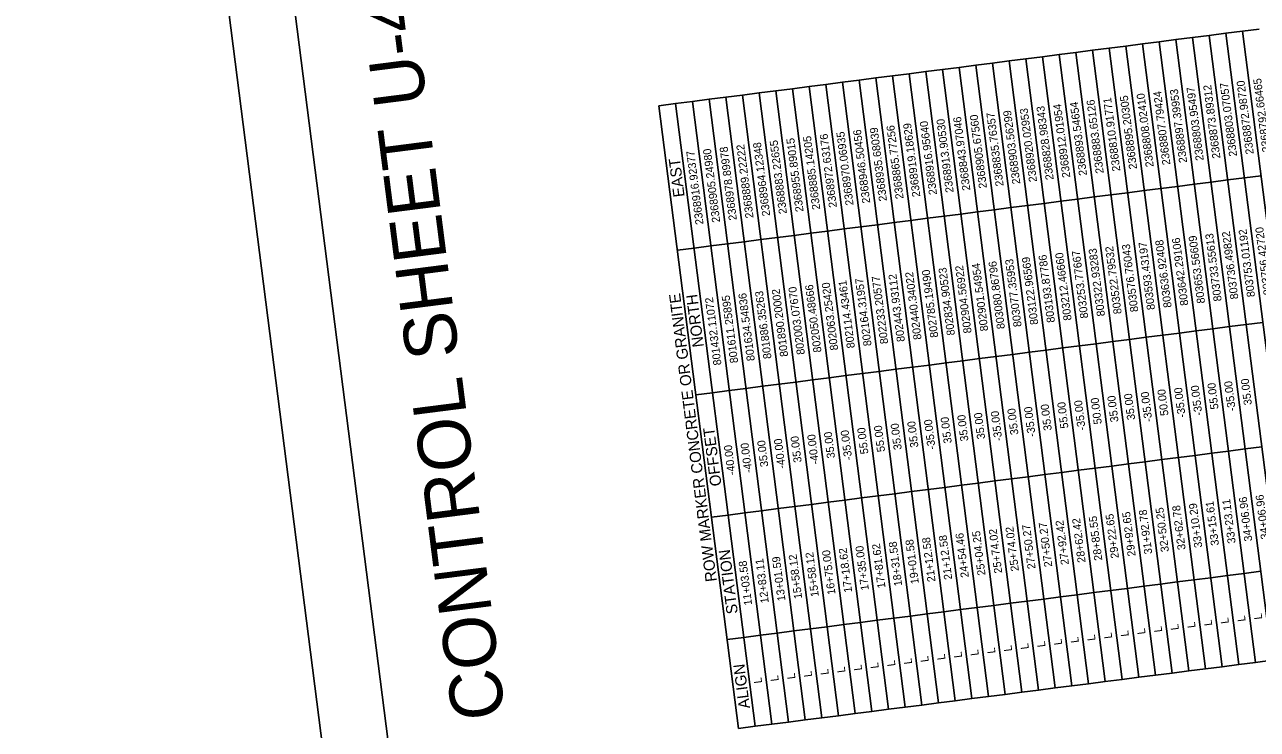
# Model space of a CAD drawing. Extents: x 2364621 to 2374814, y 792603 to 806745.
# Drawn here: x 2364621 to 2368280, y 798784 to 800875 of the extents above; entities that cross this region are included whole.
import ezdxf

# ---------------------------------------------------------------- set-up
doc = ezdxf.new("R2010")
doc.units = 0
for name, color, linetype in [('CTL Sheet Border CELL', 7, 'Continuous'), ('CTL Sheet Notes CELL', 7, 'Continuous'), ('CTL Sheet Table Cell', 7, 'Continuous'), ('CTL Sheet Text', 7, 'Continuous'), ('Scratch_Level_0', 7, 'Continuous')]:
    doc.layers.add(name, color=color, linetype=linetype)

msp = doc.modelspace()

# ---------------------------------------------------------------- linework, layer by layer
at = {"layer": 'CTL Sheet Border CELL'}
msp.add_lwpolyline([(2364831.4, 805549.1), (2366316.3, 793922.1), (2374455.2, 794961.6), (2372970.2, 806588.6)], close=True, dxfattribs=at)
at = {"layer": 'CTL Sheet Table Cell'}
for p, q in [((2367988.5, 800824.4), (2368038, 800830.7)), ((2368038, 800830.7), (2368087.5, 800837.1)), ((2368274, 798983), (2368038, 800830.7)), ((2368087.5, 800837.1), (2368137, 800843.4)), ((2368323.5, 798989.3), (2368087.5, 800837.1)), ((2368137, 800843.4), (2368186.5, 800849.7)), ((2368373, 798995.6), (2368137, 800843.4)), ((2368186.5, 800849.7), (2368236, 800856)), ((2368422.5, 799001.9), (2368186.5, 800849.7)), ((2368236, 800856), (2368285.5, 800862.3)), ((2368472, 799008.2), (2368236, 800856)), ((2367691.6, 800786.5), (2367741.1, 800792.8)), ((2367741.1, 800792.8), (2367790.6, 800799.1)), ((2367977.1, 798945), (2367741.1, 800792.8)), ((2367790.6, 800799.1), (2367840.1, 800805.5)), ((2368026.6, 798951.4), (2367790.6, 800799.1)), ((2367840.1, 800805.5), (2367889.5, 800811.8)), ((2368076.1, 798957.7), (2367840.1, 800805.5)), ((2367889.5, 800811.8), (2367939, 800818.1)), ((2368125.5, 798964), (2367889.5, 800811.8)), ((2367939, 800818.1), (2367988.5, 800824.4)), ((2368175, 798970.3), (2367939, 800818.1)), ((2368224.5, 798976.6), (2367988.5, 800824.4)), ((2367394.6, 800748.6), (2367444.1, 800754.9)), ((2367444.1, 800754.9), (2367493.6, 800761.2)), ((2367680.1, 798907.1), (2367444.1, 800754.9)), ((2367493.6, 800761.2), (2367543.1, 800767.5)), ((2367729.6, 798913.4), (2367493.6, 800761.2)), ((2367543.1, 800767.5), (2367592.6, 800773.8)), ((2367779.1, 798919.8), (2367543.1, 800767.5)), ((2367592.6, 800773.8), (2367642.1, 800780.2)), ((2367828.6, 798926.1), (2367592.6, 800773.8)), ((2367642.1, 800780.2), (2367691.6, 800786.5)), ((2367878.1, 798932.4), (2367642.1, 800780.2)), ((2367927.6, 798938.7), (2367691.6, 800786.5)), ((2367147.1, 800717), (2367196.6, 800723.3)), ((2367196.6, 800723.3), (2367246.1, 800729.6)), ((2367432.6, 798875.5), (2367196.6, 800723.3)), ((2367246.1, 800729.6), (2367295.6, 800735.9)), ((2367482.1, 798881.8), (2367246.1, 800729.6)), ((2367295.6, 800735.9), (2367345.1, 800742.2)), ((2367531.6, 798888.1), (2367295.6, 800735.9)), ((2367345.1, 800742.2), (2367394.6, 800748.6)), ((2367581.1, 798894.5), (2367345.1, 800742.2)), ((2367630.6, 798900.8), (2367394.6, 800748.6)), ((2366850.2, 800679), (2366899.7, 800685.3)), ((2366899.7, 800685.3), (2366949.2, 800691.7)), ((2367135.7, 798837.6), (2366899.7, 800685.3)), ((2366949.2, 800691.7), (2366998.7, 800698)), ((2367185.2, 798843.9), (2366949.2, 800691.7)), ((2366998.7, 800698), (2367048.2, 800704.3)), ((2367234.7, 798850.2), (2366998.7, 800698)), ((2367048.2, 800704.3), (2367097.6, 800710.6)), ((2367284.1, 798856.5), (2367048.2, 800704.3)), ((2367097.6, 800710.6), (2367147.1, 800717)), ((2367333.6, 798862.9), (2367097.6, 800710.6)), ((2367383.1, 798869.2), (2367147.1, 800717)), ((2366553.2, 800641.1), (2366602.7, 800647.4)), ((2366602.7, 800647.4), (2366652.2, 800653.7)), ((2366838.7, 798799.6), (2366602.7, 800647.4)), ((2366652.2, 800653.7), (2366701.7, 800660.1)), ((2366888.2, 798806), (2366652.2, 800653.7)), ((2366701.7, 800660.1), (2366751.2, 800666.4)), ((2366937.7, 798812.3), (2366701.7, 800660.1)), ((2366751.2, 800666.4), (2366800.7, 800672.7)), ((2366987.2, 798818.6), (2366751.2, 800666.4)), ((2366800.7, 800672.7), (2366850.2, 800679)), ((2367036.7, 798824.9), (2366800.7, 800672.7)), ((2367086.2, 798831.3), (2366850.2, 800679)), ((2366503.7, 800634.8), (2366553.2, 800641.1)), ((2366739.7, 798787), (2366503.7, 800634.8)), ((2366789.2, 798793.3), (2366553.2, 800641.1)), ((2368241.3, 800420.8), (2368290.8, 800427.1)), ((2367944.3, 800382.8), (2367993.8, 800389.1)), ((2367993.8, 800389.1), (2368043.3, 800395.5)), ((2368043.3, 800395.5), (2368092.8, 800401.8)), ((2368092.8, 800401.8), (2368142.3, 800408.1)), ((2368142.3, 800408.1), (2368191.8, 800414.4)), ((2368191.8, 800414.4), (2368241.3, 800420.8)), ((2367647.4, 800344.9), (2367696.9, 800351.2)), ((2367696.9, 800351.2), (2367746.4, 800357.5)), ((2367746.4, 800357.5), (2367795.9, 800363.9)), ((2367795.9, 800363.9), (2367845.3, 800370.2)), ((2367845.3, 800370.2), (2367894.8, 800376.5)), ((2367894.8, 800376.5), (2367944.3, 800382.8)), ((2367399.9, 800313.3), (2367449.4, 800319.6)), ((2367449.4, 800319.6), (2367498.9, 800325.9)), ((2367498.9, 800325.9), (2367548.4, 800332.3)), ((2367548.4, 800332.3), (2367597.9, 800338.6)), ((2367597.9, 800338.6), (2367647.4, 800344.9)), ((2367102.9, 800275.4), (2367152.4, 800281.7)), ((2367152.4, 800281.7), (2367201.9, 800288)), ((2367201.9, 800288), (2367251.4, 800294.3)), ((2367251.4, 800294.3), (2367300.9, 800300.6)), ((2367300.9, 800300.6), (2367350.4, 800307)), ((2367350.4, 800307), (2367399.9, 800313.3)), ((2366806, 800237.4), (2366855.5, 800243.8)), ((2366855.5, 800243.8), (2366905, 800250.1)), ((2366905, 800250.1), (2366954.5, 800256.4)), ((2366954.5, 800256.4), (2367003.9, 800262.7)), ((2367003.9, 800262.7), (2367053.4, 800269)), ((2367053.4, 800269), (2367102.9, 800275.4)), ((2366558.5, 800205.8), (2366608, 800212.2)), ((2366608, 800212.2), (2366657.5, 800218.5)), ((2366657.5, 800218.5), (2366707, 800224.8)), ((2366707, 800224.8), (2366756.5, 800231.1)), ((2366756.5, 800231.1), (2366806, 800237.4)), ((2368197.1, 799979.2), (2368246.6, 799985.5)), ((2368246.6, 799985.5), (2368296.1, 799991.8)), ((2367949.6, 799947.6), (2367999.1, 799953.9)), ((2367999.1, 799953.9), (2368048.6, 799960.2)), ((2368048.6, 799960.2), (2368098.1, 799966.5)), ((2368098.1, 799966.5), (2368147.6, 799972.8)), ((2368147.6, 799972.8), (2368197.1, 799979.2)), ((2367652.7, 799909.6), (2367702.2, 799916)), ((2367702.2, 799916), (2367751.6, 799922.3)), ((2367751.6, 799922.3), (2367801.1, 799928.6)), ((2367801.1, 799928.6), (2367850.6, 799934.9)), ((2367850.6, 799934.9), (2367900.1, 799941.2)), ((2367900.1, 799941.2), (2367949.6, 799947.6)), ((2367355.7, 799871.7), (2367405.2, 799878)), ((2367405.2, 799878), (2367454.7, 799884.3)), ((2367454.7, 799884.3), (2367504.2, 799890.7)), ((2367504.2, 799890.7), (2367553.7, 799897)), ((2367553.7, 799897), (2367603.2, 799903.3)), ((2367603.2, 799903.3), (2367652.7, 799909.6)), ((2367058.7, 799833.8), (2367108.2, 799840.1)), ((2367108.2, 799840.1), (2367157.7, 799846.4)), ((2367157.7, 799846.4), (2367207.2, 799852.7)), ((2367207.2, 799852.7), (2367256.7, 799859.1)), ((2367256.7, 799859.1), (2367306.2, 799865.4)), ((2367306.2, 799865.4), (2367355.7, 799871.7)), ((2366811.3, 799802.2), (2366860.8, 799808.5)), ((2366860.8, 799808.5), (2366910.3, 799814.8)), ((2366910.3, 799814.8), (2366959.7, 799821.1)), ((2366959.7, 799821.1), (2367009.2, 799827.5)), ((2367009.2, 799827.5), (2367058.7, 799833.8)), ((2366613.3, 799776.9), (2366662.8, 799783.2)), ((2366662.8, 799783.2), (2366712.3, 799789.5)), ((2366712.3, 799789.5), (2366761.8, 799795.8)), ((2366761.8, 799795.8), (2366811.3, 799802.2)), ((2368243.4, 799616.2), (2368292.9, 799622.5)), ((2367946.5, 799578.3), (2367996, 799584.6)), ((2367996, 799584.6), (2368045.5, 799590.9)), ((2368045.5, 799590.9), (2368095, 799597.2)), ((2368095, 799597.2), (2368144.5, 799603.6)), ((2368144.5, 799603.6), (2368194, 799609.9)), ((2368194, 799609.9), (2368243.4, 799616.2)), ((2367649.5, 799540.4), (2367699, 799546.7)), ((2367699, 799546.7), (2367748.5, 799553)), ((2367748.5, 799553), (2367798, 799559.3)), ((2367798, 799559.3), (2367847.5, 799565.6)), ((2367847.5, 799565.6), (2367897, 799572)), ((2367897, 799572), (2367946.5, 799578.3)), ((2367402.1, 799508.7), (2367451.5, 799515.1)), ((2367451.5, 799515.1), (2367501, 799521.4)), ((2367501, 799521.4), (2367550.5, 799527.7)), ((2367550.5, 799527.7), (2367600, 799534)), ((2367600, 799534), (2367649.5, 799540.4)), ((2367105.1, 799470.8), (2367154.6, 799477.1)), ((2367154.6, 799477.1), (2367204.1, 799483.5)), ((2367204.1, 799483.5), (2367253.6, 799489.8)), ((2367253.6, 799489.8), (2367303.1, 799496.1)), ((2367303.1, 799496.1), (2367352.6, 799502.4)), ((2367352.6, 799502.4), (2367402.1, 799508.7)), ((2366808.1, 799432.9), (2366857.6, 799439.2)), ((2366857.6, 799439.2), (2366907.1, 799445.5)), ((2366907.1, 799445.5), (2366956.6, 799451.9)), ((2366956.6, 799451.9), (2367006.1, 799458.2)), ((2367006.1, 799458.2), (2367055.6, 799464.5)), ((2367055.6, 799464.5), (2367105.1, 799470.8)), ((2366659.6, 799413.9), (2366709.1, 799420.2)), ((2366709.1, 799420.2), (2366758.6, 799426.6)), ((2366758.6, 799426.6), (2366808.1, 799432.9)), ((2367992.8, 799215.3), (2368042.3, 799221.6)), ((2368042.3, 799221.6), (2368091.8, 799228)), ((2368091.8, 799228), (2368141.3, 799234.3)), ((2368141.3, 799234.3), (2368190.8, 799240.6)), ((2368190.8, 799240.6), (2368240.3, 799246.9)), ((2368240.3, 799246.9), (2368289.8, 799253.3)), ((2367695.9, 799177.4), (2367745.4, 799183.7)), ((2367745.4, 799183.7), (2367794.9, 799190)), ((2367794.9, 799190), (2367844.4, 799196.4)), ((2367844.4, 799196.4), (2367893.9, 799202.7)), ((2367893.9, 799202.7), (2367943.3, 799209)), ((2367943.3, 799209), (2367992.8, 799215.3)), ((2367398.9, 799139.5), (2367448.4, 799145.8)), ((2367448.4, 799145.8), (2367497.9, 799152.1)), ((2367497.9, 799152.1), (2367547.4, 799158.4)), ((2367547.4, 799158.4), (2367596.9, 799164.8)), ((2367596.9, 799164.8), (2367646.4, 799171.1)), ((2367646.4, 799171.1), (2367695.9, 799177.4)), ((2367102, 799101.5), (2367151.4, 799107.9)), ((2367151.4, 799107.9), (2367200.9, 799114.2)), ((2367200.9, 799114.2), (2367250.4, 799120.5)), ((2367250.4, 799120.5), (2367299.9, 799126.8)), ((2367299.9, 799126.8), (2367349.4, 799133.1)), ((2367349.4, 799133.1), (2367398.9, 799139.5)), ((2366854.5, 799069.9), (2366904, 799076.3)), ((2366904, 799076.3), (2366953.5, 799082.6)), ((2366953.5, 799082.6), (2367003, 799088.9)), ((2367003, 799088.9), (2367052.5, 799095.2)), ((2367052.5, 799095.2), (2367102, 799101.5)), ((2366706, 799051), (2366755.5, 799057.3)), ((2366755.5, 799057.3), (2366805, 799063.6)), ((2366805, 799063.6), (2366854.5, 799069.9)), ((2368076.1, 798957.7), (2368125.5, 798964)), ((2368125.5, 798964), (2368175, 798970.3)), ((2368175, 798970.3), (2368224.5, 798976.6)), ((2368224.5, 798976.6), (2368274, 798983)), ((2368274, 798983), (2368323.5, 798989.3)), ((2367779.1, 798919.8), (2367828.6, 798926.1)), ((2367828.6, 798926.1), (2367878.1, 798932.4)), ((2367878.1, 798932.4), (2367927.6, 798938.7)), ((2367927.6, 798938.7), (2367977.1, 798945)), ((2367977.1, 798945), (2368026.6, 798951.4)), ((2368026.6, 798951.4), (2368076.1, 798957.7)), ((2367482.1, 798881.8), (2367531.6, 798888.1)), ((2367531.6, 798888.1), (2367581.1, 798894.5)), ((2367581.1, 798894.5), (2367630.6, 798900.8)), ((2367630.6, 798900.8), (2367680.1, 798907.1)), ((2367680.1, 798907.1), (2367729.6, 798913.4)), ((2367729.6, 798913.4), (2367779.1, 798919.8)), ((2367234.7, 798850.2), (2367284.1, 798856.5)), ((2367284.1, 798856.5), (2367333.6, 798862.9)), ((2367333.6, 798862.9), (2367383.1, 798869.2)), ((2367383.1, 798869.2), (2367432.6, 798875.5)), ((2367432.6, 798875.5), (2367482.1, 798881.8)), ((2366937.7, 798812.3), (2366987.2, 798818.6)), ((2366987.2, 798818.6), (2367036.7, 798824.9)), ((2367036.7, 798824.9), (2367086.2, 798831.3)), ((2367086.2, 798831.3), (2367135.7, 798837.6)), ((2367135.7, 798837.6), (2367185.2, 798843.9)), ((2367185.2, 798843.9), (2367234.7, 798850.2)), ((2366739.7, 798787), (2366789.2, 798793.3)), ((2366789.2, 798793.3), (2366838.7, 798799.6)), ((2366838.7, 798799.6), (2366888.2, 798806)), ((2366888.2, 798806), (2366937.7, 798812.3))]:
    msp.add_line(p, q, dxfattribs=at)
at = {"layer": 'Scratch_Level_0'}
msp.add_lwpolyline([(2374814.3, 793692), (2373147.1, 806745.2), (2364620.8, 805656.2), (2366287.9, 792603)], close=True, dxfattribs=at)

# ---------------------------------------------------------------- texts
at = {"layer": 'CTL Sheet Border CELL'}
msp.add_text('SURVEY CONTROL SHEET U-4762', height=156.286, rotation=97.2784, dxfattribs=at).set_placement((2366164.2, 797911.8))
at = {"layer": 'CTL Sheet Notes CELL'}
for s, height, p in [('EAST', 33.26, (2366580, 800365.6)), ('ROW MARKER CONCRETE OR GRANITE', 33.264, (2366675.5, 799224.3)), ('NORTH', 33.26, (2366636.9, 799920.2)), ('OFFSET', 33.26, (2366689.6, 799507.9)), ('STATION', 33.26, (2366738, 799128.6)), ('ALIGN', 33.26, (2366773.9, 798847.9))]:
    msp.add_text(s, height=height, rotation=97.2784, dxfattribs=at).set_placement(p)
at = {"layer": 'CTL Sheet Text'}
for s, height, p in [('2368897.39953', 23.76, (2368071.4, 800466.5)), ('2368803.95497', 23.76, (2368120.9, 800472.8)), ('2368873.89312', 23.76, (2368170.4, 800479.2)), ('2368803.07057', 23.76, (2368219.9, 800485.5)), ('2368872.98720', 23.76, (2368269.3, 800491.8)), ('2368792.66465', 23.76, (2368318.8, 800498.1)), ('2368893.54654', 23.76, (2367774.4, 800428.6)), ('2368883.65126', 23.76, (2367823.9, 800434.9)), ('2368810.91771', 23.76, (2367873.4, 800441.2)), ('2368895.20305', 23.76, (2367922.9, 800447.6)), ('2368808.02410', 23.76, (2367972.4, 800453.9)), ('2368807.79424', 23.76, (2368021.9, 800460.2)), ('2368905.67560', 23.76, (2367477.4, 800390.7)), ('2368835.76357', 23.76, (2367526.9, 800397)), ('2368903.56299', 23.76, (2367576.4, 800403.3)), ('2368920.02953', 23.76, (2367625.9, 800409.6)), ('2368828.98343', 23.76, (2367675.4, 800415.9)), ('2368912.01954', 23.76, (2367724.9, 800422.3)), ('2368865.77256', 23.76, (2367230, 800359.1)), ('2368919.18629', 23.76, (2367279.5, 800365.4)), ('2368916.95640', 23.76, (2367329, 800371.7)), ('2368913.90530', 23.76, (2367378.5, 800378)), ('2368843.97046', 23.76, (2367428, 800384.3)), ('2368955.89015', 23.76, (2366933, 800321.1)), ('2368885.14205', 23.76, (2366982.5, 800327.4)), ('2368972.63176', 23.76, (2367032, 800333.8)), ('2368970.06935', 23.76, (2367081.5, 800340.1)), ('2368946.50456', 23.76, (2367131, 800346.4)), ('2368935.68039', 23.76, (2367180.5, 800352.7)), ('2368916.92377', 23.76, (2366636, 800283.2)), ('2368905.24980', 23.76, (2366685.5, 800289.5)), ('2368978.89978', 23.76, (2366735, 800295.8)), ('2368889.22222', 23.76, (2366784.5, 800302.2)), ('2368964.12348', 23.76, (2366834, 800308.5)), ('2368883.22655', 23.76, (2366883.5, 800314.8)), ('803642.29106', 23.76, (2368075.2, 800042.9)), ('803653.56609', 23.76, (2368124.7, 800049.3)), ('803733.55613', 23.76, (2368174.2, 800055.6)), ('803736.49822', 23.76, (2368223.7, 800061.9)), ('803753.01192', 23.76, (2368273.1, 800068.2)), ('803756.42720', 23.76, (2368322.6, 800074.5)), ('803322.93283', 23.76, (2367827.7, 800011.3)), ('803522.79532', 23.76, (2367877.2, 800017.7)), ('803576.76043', 23.76, (2367926.7, 800024)), ('803593.43197', 23.76, (2367976.2, 800030.3)), ('803636.92408', 23.76, (2368025.7, 800036.6)), ('803080.86796', 23.76, (2367530.7, 799973.4)), ('803077.35953', 23.76, (2367580.2, 799979.7)), ('803122.96569', 23.76, (2367629.7, 799986)), ('803193.87786', 23.76, (2367679.2, 799992.4)), ('803212.46660', 23.76, (2367728.7, 799998.7)), ('803253.77667', 23.76, (2367778.2, 800005)), ('802443.93112', 23.76, (2367233.8, 799935.5)), ('802440.34022', 23.76, (2367283.3, 799941.8)), ('802785.19490', 23.76, (2367332.8, 799948.1)), ('802834.90523', 23.76, (2367382.3, 799954.4)), ('802904.56922', 23.76, (2367431.8, 799960.8)), ('802901.54954', 23.76, (2367481.2, 799967.1)), ('802003.07670', 23.76, (2366936.8, 799897.5)), ('802050.48666', 23.76, (2366986.3, 799903.9)), ('802063.25420', 23.76, (2367035.8, 799910.2)), ('802114.43461', 23.76, (2367085.3, 799916.5)), ('802164.31957', 23.76, (2367134.8, 799922.8)), ('802233.20577', 23.76, (2367184.3, 799929.2)), ('801432.11072', 23.76, (2366689.3, 799865.9)), ('801611.25895', 23.76, (2366738.8, 799872.3)), ('801634.54836', 23.76, (2366788.3, 799878.6)), ('801886.35263', 23.76, (2366837.8, 799884.9)), ('801890.20002', 23.76, (2366887.3, 799891.2)), ('-35.00', 23.76, (2368116.8, 799717.1)), ('55.00', 23.76, (2368164.8, 799735.1)), ('-35.00', 23.76, (2368215.8, 799729.8)), ('35.00', 23.76, (2368263.8, 799747.8)), ('50.00', 23.76, (2367818.3, 799690.9)), ('35.00', 23.76, (2367867.8, 799697.2)), ('35.00', 23.76, (2367917.3, 799703.5)), ('-35.00', 23.76, (2367968.3, 799698.2)), ('50.00', 23.76, (2368016.3, 799716.2)), ('-35.00', 23.76, (2368067.3, 799710.8)), ('35.00', 23.76, (2367570.9, 799659.3)), ('-35.00', 23.76, (2367621.8, 799653.9)), ('35.00', 23.76, (2367669.8, 799671.9)), ('55.00', 23.76, (2367719.3, 799678.3)), ('-35.00', 23.76, (2367770.3, 799672.9)), ('35.00', 23.76, (2367273.9, 799621.4)), ('-35.00', 23.76, (2367324.9, 799616)), ('35.00', 23.76, (2367372.9, 799634)), ('35.00', 23.76, (2367422.4, 799640.3)), ('35.00', 23.76, (2367471.9, 799646.7)), ('-35.00', 23.76, (2367522.9, 799641.3)), ('-40.00', 23.76, (2366978.4, 799571.7)), ('35.00', 23.76, (2367026.4, 799589.8)), ('-35.00', 23.76, (2367077.4, 799584.4)), ('55.00', 23.76, (2367125.4, 799602.4)), ('55.00', 23.76, (2367174.9, 799608.7)), ('35.00', 23.76, (2367224.4, 799615)), ('-40.00', 23.76, (2366731, 799540.1)), ('-40.00', 23.76, (2366780.4, 799546.5)), ('35.00', 23.76, (2366828.4, 799564.5)), ('-40.00', 23.76, (2366879.4, 799559.1)), ('35.00', 23.76, (2366927.4, 799577.1)), ('34+06.96', 23.76, (2368265.1, 799343.4)), ('34+06.96', 23.76, (2368314.6, 799349.8)), ('32+50.25', 23.76, (2368017.6, 799311.8)), ('32+62.78', 23.76, (2368067.1, 799318.2)), ('33+10.29', 23.76, (2368116.6, 799324.5)), ('33+15.61', 23.76, (2368166.1, 799330.8)), ('33+23.11', 23.76, (2368215.6, 799337.1)), ('27+92.42', 23.76, (2367720.7, 799273.9)), ('28+62.42', 23.76, (2367770.2, 799280.2)), ('28+85.55', 23.76, (2367819.7, 799286.5)), ('29+22.65', 23.76, (2367869.2, 799292.9)), ('29+92.65', 23.76, (2367918.7, 799299.2)), ('31+92.78', 23.76, (2367968.1, 799305.5)), ('24+54.46', 23.76, (2367423.7, 799236)), ('25+04.25', 23.76, (2367473.2, 799242.3)), ('25+74.02', 23.76, (2367522.7, 799248.6)), ('25+74.02', 23.76, (2367572.2, 799254.9)), ('27+50.27', 23.76, (2367621.7, 799261.3)), ('27+50.27', 23.76, (2367671.2, 799267.6)), ('17+35.00', 23.76, (2367126.8, 799198.1)), ('17+81.62', 23.76, (2367176.2, 799204.4)), ('18+31.58', 23.76, (2367225.7, 799210.7)), ('19+01.58', 23.76, (2367275.2, 799217)), ('21+12.58', 23.76, (2367324.7, 799223.3)), ('21+12.58', 23.76, (2367374.2, 799229.7)), ('12+83.11', 23.76, (2366829.8, 799160.1)), ('13+01.59', 23.76, (2366879.3, 799166.4)), ('15+58.12', 23.76, (2366928.8, 799172.8)), ('15+58.12', 23.76, (2366978.3, 799179.1)), ('16+75.00', 23.76, (2367027.8, 799185.4)), ('17+18.62', 23.76, (2367077.3, 799191.7)), ('11+03.58', 23.76, (2366780.3, 799153.8)), ('L', 23.8, (2368146.2, 799092.9)), ('L', 23.8, (2368195.7, 799099.2)), ('L', 23.8, (2368245.2, 799105.5)), ('L', 23.8, (2368294.7, 799111.8)), ('L', 23.8, (2367849.3, 799054.9)), ('L', 23.8, (2367898.7, 799061.2)), ('L', 23.8, (2367948.2, 799067.6)), ('L', 23.8, (2367997.7, 799073.9)), ('L', 23.8, (2368047.2, 799080.2)), ('L', 23.8, (2368096.7, 799086.5)), ('L', 23.8, (2367601.8, 799023.3)), ('L', 23.8, (2367651.3, 799029.6)), ('L', 23.8, (2367700.8, 799036)), ('L', 23.8, (2367750.3, 799042.3)), ('L', 23.8, (2367799.8, 799048.6)), ('L', 23.8, (2367304.8, 798985.4)), ('L', 23.8, (2367354.3, 798991.7)), ('L', 23.8, (2367403.8, 798998)), ('L', 23.8, (2367453.3, 799004.4)), ('L', 23.8, (2367502.8, 799010.7)), ('L', 23.8, (2367552.3, 799017)), ('L', 23.8, (2367007.9, 798947.5)), ('L', 23.8, (2367057.3, 798953.8)), ('L', 23.8, (2367106.8, 798960.1)), ('L', 23.8, (2367156.3, 798966.4)), ('L', 23.8, (2367205.8, 798972.8)), ('L', 23.8, (2367255.3, 798979.1)), ('L', 23.8, (2366809.9, 798922.2)), ('L', 23.8, (2366859.4, 798928.5)), ('L', 23.8, (2366908.9, 798934.8)), ('L', 23.8, (2366958.4, 798941.1))]:
    msp.add_text(s, height=height, rotation=97.2784, dxfattribs=at).set_placement(p)

doc.saveas('drawing.dxf')
